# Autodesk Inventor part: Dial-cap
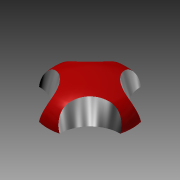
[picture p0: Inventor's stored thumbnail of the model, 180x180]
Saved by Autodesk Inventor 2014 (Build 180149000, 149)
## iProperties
Shininess: 64.0
Length Units: 11272
Angle Units: 11279
Time Units: 11290
Mass Units: 11286
Length Display Precision: 3
Angle Display Precision: 2
Compacted: True
Created: 2001-11
Part Number: Dial-cap
Document SubType Name: Modeling
Designer: Autodesk, Inc.
Mass: 1.44224 g
Surface Area: 10.3588 cm^2
Volume: 1.44224 cm^3
Density: 1 g/cm^3
Material: Generic
Appearance: Smooth - Red
Density: 0.0
Volumn: 0.0
Area: 0.0
PropertySet Name: Model Information
Control State: 0
Master: False
Checked Out: False
Author: Autodesk, Inc.
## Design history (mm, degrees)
sketch "Sketch1"
  geometry: L1 (133.744, 47.494)-(133.744, 91.062); L2 (145.889, 43.525)-(145.889, 43.609); L3 (138.904, 43.525)-(145.889, 43.525); L4 (138.904, 44.319)-(138.904, 43.525); L5 (136.7, 44.319)-(138.904, 44.319); L6 (136.7, 47.494)-(136.7, 44.319); L7 (133.744, 47.494)-(136.7, 47.494); L8 (133.744, 54.846)-(133.744, 91.062); A1 r 23.812 centre (133.744, 26.857) between (141.999, 49.192) and (133.744, 50.669); A2 r 5.953 centre (139.936, 43.609) between (145.889, 43.609) and (141.999, 49.192)
  constraints: 16 end point, 4 point on circle, 4 vertical, 3 horizontal, 2 centre point, 2 point on line, 1 tangent, 1 other
revolve "RevolutionFull1" sketch "Sketch1" stored, may be unused: angle "d0" = 360 deg
sketch "Sketch3"
  geometry: A1 r 12.144 centre (0, 0) between (-2.977, -11.774) and (-11.774, -2.977) reference; A2 r 8.797 centre (-11.774, -11.774) between (-2.977, -11.774) and (-11.774, -2.977)
  constraints: 4 point on circle, 1 centre point
extrude "ExtrusionThru1" cut sketch "Sketch3" stored distance "d3" = 3.302; taper "d4" = 15 deg
pattern_circular "PolarArray1" dims angle "d7" = 360 deg
sketch "Sketch5"
  geometry: L1 (-2.887, 1.667)-(-2.887, -1.667); L2 (0, 3.334)-(-2.887, 1.667); L3 (2.887, 1.667)-(0, 3.334); L4 (2.887, -1.667)-(2.887, 1.667); L5 (0, -3.334)-(2.887, -1.667); L6 (-2.887, -1.667)-(0, -3.334)
  constraints: 12 end point, 2 parallel, 2 vertical
extrude "ExtrusionToPlane1" cut sketch "Sketch5" stored distance "d8" = 3.302; taper "d9" = 0 deg
body "Solid1"
other parameters: "d1" = 0, "d2" = 0
